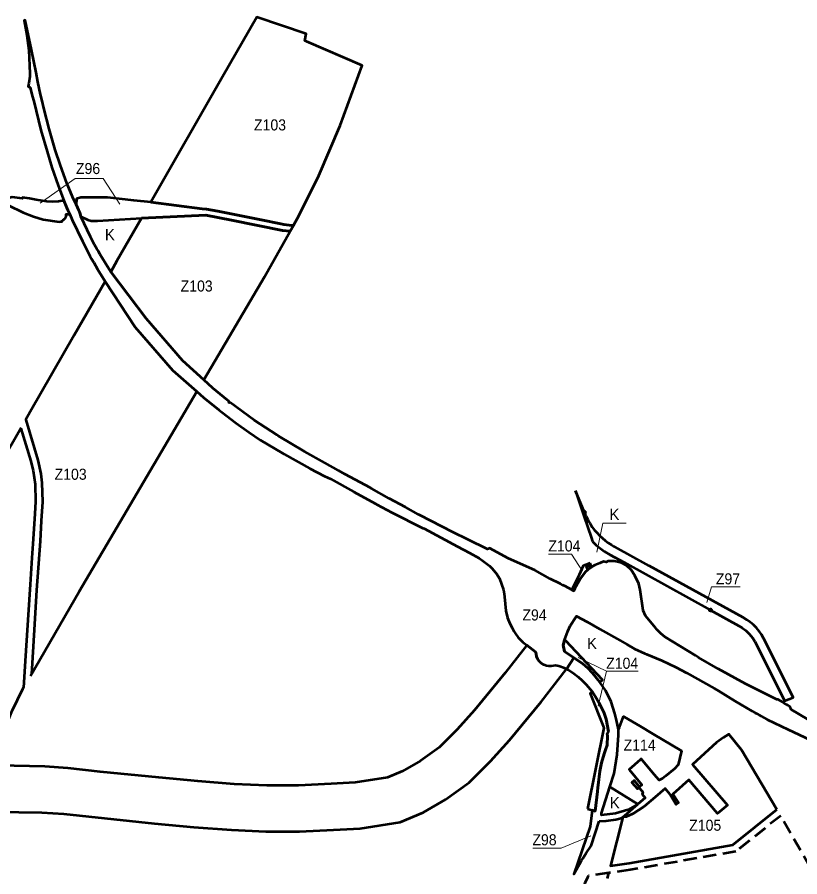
# Model space of a CAD drawing. Extents: x -650246 to -642674, y -1074280 to -1066767.
# Drawn here: x -647810 to -646112, y -1069193 to -1067326 of the extents above; entities that cross this region are included whole.
import ezdxf

# ---------------------------------------------------------------- set-up
doc = ezdxf.new("R2010")
doc.units = 0
doc.header["$LTSCALE"] = 9.6
doc.header["$PDMODE"] = 32
doc.header["$PDSIZE"] = 4.8
doc.linetypes.add('MEDIUM_DASHED', pattern=[4.5, 3, -1.5])
for name, color, linetype, lineweight in [('44', 7, 'Continuous', 53), ('45', 7, 'Continuous', 53), ('46', 7, 'Continuous', 13), ('48', 7, 'Continuous', 13), ('61', 7, 'MEDIUM_DASHED', 53)]:
    doc.layers.add(name, color=color, linetype=linetype, lineweight=lineweight)

msp = doc.modelspace()

# ---------------------------------------------------------------- linework, layer by layer
at = {"layer": '44'}
for p, q in [((-647540.208, -1067762.876), (-647400.63, -1067756.19)), ((-646578.881, -1068401.54), (-646598.635, -1068354.436))]:
    msp.add_line(p, q, dxfattribs=at)
for points in [[(-647606.818, -1067879.061), (-647617.25, -1067861.95), (-647625.37, -1067848.86), (-647630.3, -1067841.02), (-647633.69, -1067834.31), (-647637.21, -1067829.29), (-647642.29, -1067820.76), (-647650.8, -1067803.28), (-647672.05, -1067758.98), (-647673.47, -1067753.48), (-647673.47, -1067753.48), (-647674.67, -1067748.73), (-647676.47, -1067744.5), (-647678.66, -1067739.38), (-647681.91, -1067732.74), (-647690.09, -1067716.05), (-647702.04, -1067686.86), (-647715.92, -1067648.12), (-647727.37, -1067614.33), (-647740.49, -1067568.67), (-647751.41, -1067526.58), (-647756.55, -1067505.32), (-647759.16, -1067494.01), (-647764.89, -1067466.64), (-647768.5, -1067446.04), (-647778.78, -1067397.1), (-647792.52, -1067332.74), (-647794.54, -1067333.14), (-647788.77, -1067365.03), (-647784.55, -1067398.01), (-647782.39, -1067448.34), (-647782.5, -1067455.11), (-647784.36, -1067469.6), (-647785.64, -1067477.02), (-647781.85, -1067479.19), (-647777.55, -1067496.95), (-647773.96, -1067508.48), (-647768.5, -1067529.75), (-647758.25, -1067571.79), (-647744.61, -1067617.96), (-647734.63, -1067652.57), (-647721.05, -1067691.73), (-647708.71, -1067723.99), (-647702.21, -1067740.43), (-647699.89, -1067745.24), (-647697.85, -1067749.46), (-647695.71, -1067753.9), (-647690.19, -1067766.37), (-647668.13, -1067812.76), (-647651.94, -1067844.36), (-647648.33, -1067851.17), (-647643.83, -1067859.13), (-647635.77, -1067873.43), (-647618.773, -1067899.914)], [(-647695.797, -1067753.719), (-647697.85, -1067749.46), (-647699.89, -1067745.24), (-647702.21, -1067740.43), (-647708.71, -1067723.99), (-647720.45, -1067726.49), (-647732.71, -1067727.02), (-647745.41, -1067726.6), (-647768.53, -1067722.82), (-647783.13, -1067719.68), (-647798.17, -1067717.58), (-647798.5, -1067719.67), (-647821.02, -1067717.33), (-647850.45, -1067724.77)], [(-647850.45, -1067724.77), (-647838.18, -1067731.62), (-647832.56, -1067734.22), (-647829.49, -1067734.58), (-647796.87, -1067750.25), (-647774.54, -1067758.68), (-647753.53, -1067765.58), (-647718.54, -1067770.6), (-647712.01, -1067769.63), (-647712.26, -1067767.28)], [(-647520.145, -1067727.879), (-647557, -1067724), (-647614, -1067718), (-647643, -1067718), (-647672, -1067718), (-647680.804, -1067720.745), (-647681.91, -1067732.74)], [(-647681.91, -1067732.74), (-647678.66, -1067739.38), (-647676.47, -1067744.5), (-647674.67, -1067748.73), (-647673.47, -1067753.48)], [(-647398.74, -1067743.15), (-647408.2, -1067742.37), (-647520.145, -1067727.879)], [(-647210.537, -1067778.594), (-647213.92, -1067778.26), (-647231.17, -1067776.55), (-647237.91, -1067775.18), (-647280.78, -1067766.44), (-647374.55, -1067747.34), (-647398.74, -1067743.15)], [(-647712.26, -1067767.28), (-647711.773, -1067767.135), (-647711.286, -1067766.968), (-647710.799, -1067766.777), (-647710.315, -1067766.562), (-647709.834, -1067766.324), (-647709.359, -1067766.062), (-647708.892, -1067765.776), (-647708.433, -1067765.466), (-647707.985, -1067765.133), (-647707.55, -1067764.777), (-647707.128, -1067764.398), (-647706.723, -1067763.999), (-647706.335, -1067763.579), (-647705.966, -1067763.14), (-647705.617, -1067762.683), (-647705.29, -1067762.21), (-647704.985, -1067761.721), (-647704.704, -1067761.22), (-647704.447, -1067760.707), (-647704.216, -1067760.184), (-647704.01, -1067759.653), (-647703.83, -1067759.117), (-647703.675, -1067758.576), (-647703.547, -1067758.033), (-647703.445, -1067757.489), (-647703.368, -1067756.946), (-647703.315, -1067756.406), (-647703.287, -1067755.87), (-647703.282, -1067755.341), (-647703.3, -1067754.818), (-647703.34, -1067754.304), (-647703.4, -1067753.8), (-647695.797, -1067753.719)], [(-647673.47, -1067753.48), (-647672.05, -1067758.98), (-647672.05, -1067758.98), (-647656.469, -1067766.309), (-647649.22, -1067768.38), (-647635.758, -1067768.38), (-647540.208, -1067762.876)], [(-647540.208, -1067762.876), (-647593.267, -1067855.425), (-647606.818, -1067879.061)], [(-647217.611, -1067791.149), (-647233.83, -1067789.69), (-647345.11, -1067767.28), (-647400.63, -1067756.19), (-647540.208, -1067762.876)], [(-647400.63, -1067756.19), (-647345.11, -1067767.28), (-647233.83, -1067789.69), (-647217.611, -1067791.149), (-647210.537, -1067778.594)], [(-647405.026, -1068113.904), (-647273.297, -1067889.981), (-647217.611, -1067791.149)], [(-647405.026, -1068113.904), (-647451.024, -1068071.886), (-647530.038, -1067980.839), (-647606.818, -1067879.061)], [(-647606.818, -1067879.061), (-647530.038, -1067980.839), (-647451.024, -1068071.886), (-647405.026, -1068113.904)], [(-647618.773, -1067899.914), (-647685.819, -1068016.861), (-647781.346, -1068183.485), (-647791.669, -1068201.583)], [(-647781.204, -1068756.329), (-647675.054, -1068572.919), (-647461.188, -1068209.373), (-647419.713, -1068138.871), (-647472.338, -1068093.096), (-647553.628, -1067999.427), (-647618.773, -1067899.915), (-647618.773, -1067899.914)], [(-647618.773, -1067899.914), (-647553.628, -1067999.427), (-647472.338, -1068093.096), (-647419.713, -1068138.871)], [(-646545.57, -1068511.42), (-646556.22, -1068515.84), (-646559.72, -1068517.29), (-646569.61, -1068524.1), (-646572.02, -1068526.07), (-646577.07, -1068530.2), (-646587.28, -1068545.28), (-646599.75, -1068566.49), (-646602.21, -1068571.5), (-646606.59, -1068569.33), (-646620.94, -1068561.96), (-646625.86, -1068559.47), (-646631.18, -1068556.77), (-646653.21, -1068545.58), (-646686.84, -1068526.89), (-646686.84, -1068526.89), (-646743.69, -1068501.76), (-646785.05, -1068479.12), (-646787.55, -1068480.36), (-646789.49, -1068481.31), (-646832.29, -1068460.04), (-646864.48, -1068444.64), (-646936.47, -1068407.23), (-646938.95, -1068405.8), (-646967.64, -1068390), (-647002.71, -1068371.09), (-647040.77, -1068349.4), (-647044.93, -1068347.08), (-647053.75, -1068342.11), (-647099.2, -1068318.27), (-647112.813, -1068310.564), (-647142.41, -1068293.81), (-647186.26, -1068269.45), (-647243.39, -1068235.26), (-647246.8, -1068233.08), (-647295.47, -1068201.09), (-647347.74, -1068162.54), (-647349.59, -1068163.24), (-647350.6, -1068160.26), (-647353.81, -1068157.67), (-647385.13, -1068131.51), (-647405.026, -1068113.904)], [(-647419.713, -1068138.871), (-647405.71, -1068151.74), (-647372.38, -1068179.01), (-647337.74, -1068205.67), (-647334.62, -1068208.02), (-647307.39, -1068227.44), (-647281.64, -1068244.34), (-647234.11, -1068273.04), (-647230.83, -1068274.93), (-647174.56, -1068306.35), (-647142.788, -1068322.462), (-647130.29, -1068328.8), (-647079.16, -1068357.01), (-647032.91, -1068382.51), (-647029.23, -1068384.46), (-646997.06, -1068401.37), (-646929.56, -1068435.42), (-646927.06, -1068436.66)], [(-647791.055, -1068200.507), (-647765.22, -1068287.94), (-647758.45, -1068317.66), (-647756.09, -1068337.61), (-647754.99, -1068378.21), (-647757.41, -1068419.98), (-647760.22, -1068463.96), (-647768.02, -1068570.36), (-647772.85, -1068656.41), (-647778.967, -1068752.463)], [(-647801.168, -1068218.237), (-647843.6, -1068292.629), (-647868.214, -1068337.803), (-647914.339, -1068432.512), (-647946.187, -1068510.254), (-647971.074, -1068581.98), (-647997.27, -1068674.747), (-648011.775, -1068739.718), (-648023.914, -1068809.332), (-648030.73, -1068861.213), (-648038.596, -1068968.281), (-647958.168, -1068957.73)], [(-647801.797, -1068219.339), (-647780.07, -1068290.53), (-647774.94, -1068311.47), (-647770.81, -1068340.29), (-647770.12, -1068377.5), (-647771.74, -1068404.5), (-647775.82, -1068469.74), (-647778.24, -1068499.95), (-647781.55, -1068558.38), (-647785.79, -1068623.98), (-647791.77, -1068713.23), (-647796.139, -1068781.67)], [(-646598.635, -1068354.436), (-646579.62, -1068411.29), (-646564.78, -1068455.41), (-646561.544, -1068464.842)], [(-646927.06, -1068436.66), (-646854.18, -1068475.8), (-646828.2, -1068489.61), (-646807.82, -1068501.17), (-646799.79, -1068506.39), (-646790.66, -1068513.24), (-646785.34, -1068517.77), (-646779.93, -1068522.9), (-646775.44, -1068527.74), (-646768.95, -1068535.8), (-646763.1, -1068545.18), (-646754.92, -1068569.81), (-646753.35, -1068578.6), (-646752.59, -1068584.55), (-646749.35, -1068615.18), (-646746.32, -1068630.23), (-646740.91, -1068642.34), (-646735.62, -1068652.21), (-646732.25, -1068659.06), (-646729.34, -1068663.94), (-646722.6, -1068673.11), (-646716.39, -1068679.8), (-646716.39, -1068679.8), (-646712.93, -1068683), (-646704.316, -1068689.698), (-646684.7, -1068704.95), (-646682.98, -1068714.07), (-646680.88, -1068719.28), (-646678.08, -1068723.7)], [(-646561.544, -1068464.842), (-646553.677, -1068472.283), (-646544.525, -1068479.79), (-646535.245, -1068486.342), (-646523.105, -1068493.54), (-646493.511, -1068509.855), (-646305.678, -1068613.404)], [(-646234.342, -1068629.893), (-646234.342, -1068629.892), (-646438.626, -1068517.274), (-646513.45, -1068476.025), (-646513.567, -1068475.963)], [(-646337.93, -1068712.4), (-646404.83, -1068671.52), (-646413.45, -1068664.71), (-646422.32, -1068655.58), (-646425.11, -1068652.37), (-646446.54, -1068626.14), (-646451.82, -1068614.31), (-646458.03, -1068569.26), (-646461.14, -1068556.34), (-646469.51, -1068538.15), (-646477.41, -1068526.45), (-646487.92, -1068516.87), (-646498.48, -1068511.26), (-646507.4, -1068508.45), (-646514.39, -1068507.56), (-646528.18, -1068507.58), (-646531.9, -1068509.25), (-646537.71, -1068508.16), (-646545.57, -1068511.42)], [(-646305.678, -1068613.404), (-646243.997, -1068647.407), (-646236.707, -1068651.891), (-646228.691, -1068658.051), (-646221.348, -1068665.144), (-646213.659, -1068674.696), (-646209.179, -1068681.795), (-646204.654, -1068690.937), (-646145.083, -1068810.83), (-646126.317, -1068803.654), (-646186.371, -1068682.825)], [(-646602.095, -1068716.98), (-646622.01, -1068703.3), (-646625.35, -1068689.7), (-646622.68, -1068678.75), (-646615.19, -1068659.11), (-646609.7, -1068647.84), (-646597.4, -1068628.74), (-646596.28, -1068626.52), (-646596.28, -1068626.52), (-646573.14, -1068638.98), (-646545.73, -1068654.81), (-646545.73, -1068654.81), (-646501.64, -1068679.81), (-646486.23, -1068688.54), (-646470.65, -1068697.38), (-646448.02, -1068707.99), (-646444.51, -1068709.64), (-646411.3, -1068723.11), (-646380.94, -1068737.81), (-646357.87, -1068749.64), (-646297.08, -1068783.8), (-646288.37, -1068789.04), (-646251.73, -1068811.04), (-646214.92, -1068832.85), (-646208.7, -1068836.39), (-646205.48, -1068838.23), (-646199.24, -1068841.79), (-646195.52, -1068843.92), (-646182.57, -1068851.3), (-646137.23, -1068872.6), (-646089.63, -1068895.5)], [(-646704.316, -1068689.698), (-646725.374, -1068716.786), (-646751.116, -1068749.975), (-646817.718, -1068830.545), (-646855.506, -1068872.883), (-646894.206, -1068911.595), (-646934.465, -1068940.759)], [(-646617.991, -1068741.504), (-646622.62, -1068739.32), (-646634.37, -1068735.27), (-646642.04, -1068733.74), (-646651.21, -1068734.99), (-646656.47, -1068735.13), (-646661.5, -1068734.35), (-646667.17, -1068732.38), (-646673.16, -1068728.69), (-646678.08, -1068723.7), (-646680.88, -1068719.28), (-646682.98, -1068714.07), (-646684.7, -1068704.95), (-646704.316, -1068689.698)], [(-646075.56, -1068861.95), (-646130.68, -1068829.21), (-646132.62, -1068823.54), (-646136.99, -1068820.88), (-646140.73, -1068818.61), (-646146.85, -1068814.88), (-646150.26, -1068812.81), (-646159.1, -1068807.43), (-646161.45, -1068807.54), (-646229.44, -1068773.53), (-646288.59, -1068740.88), (-646331.26, -1068716.25), (-646337.93, -1068712.4)], [(-646618.655, -1068742.359), (-646617.991, -1068741.504), (-646617.991, -1068741.503), (-646602.095, -1068716.98)], [(-646539.08, -1068779.481), (-646545.32, -1068769.89), (-646561.5, -1068750.22), (-646571.91, -1068739.54), (-646583.49, -1068729.76), (-646602.095, -1068716.98), (-646617.991, -1068741.503)], [(-647065.688, -1069087.73), (-646978.92, -1069073.93), (-646929.186, -1069052.925), (-646880.163, -1069024.903), (-646829.104, -1068987.917), (-646782.784, -1068941.581), (-646741.85, -1068895.719), (-646673.05, -1068812.491), (-646618.655, -1068742.359), (-646617.991, -1068741.504)], [(-646617.991, -1068741.503), (-646613.44, -1068743.65), (-646601.86, -1068751.01), (-646592.53, -1068758.66), (-646583.98, -1068766.42), (-646575.28, -1068775.04), (-646562.49, -1068790.69), (-646554.8, -1068801.98)], [(-647864.531, -1068951.823), (-647846.989, -1068896.545), (-647820.883, -1068832.117), (-647797.632, -1068784.713), (-647795.185, -1068780.485)], [(-646509.323, -1068852.529), (-646513.27, -1068838.37), (-646521.18, -1068812.95), (-646532.92, -1068788.95), (-646539.08, -1068779.481)], [(-646554.8, -1068801.98), (-646547.68, -1068814.22), (-646547.433, -1068814.73)], [(-646547.433, -1068814.73), (-646537.35, -1068835.56), (-646532.16, -1068850.47), (-646526.64, -1068877.47), (-646530.06, -1068882.16)], [(-646524, -1068997), (-646514.91, -1068968.48), (-646514.91, -1068968.48), (-646512.07, -1068954.68), (-646507.91, -1068927.47), (-646505.12, -1068885.31), (-646505.17, -1068872.78), (-646509.323, -1068852.529)], [(-646530.06, -1068882.16), (-646528.92, -1068886.55), (-646529.44, -1068906.81), (-646533.28, -1068917.17)], [(-646533.28, -1068917.17), (-646536.54, -1068925.95), (-646542.16, -1068945.12), (-646545.42, -1068963.3), (-646549.17, -1068993.71), (-646549.81, -1068998.88), (-646550.89, -1069007.7), (-646555.84, -1069050.22), (-646559.8, -1069048.98), (-646562.61, -1069048.08)], [(-647749.978, -1068953.416), (-647850.043, -1068951.099), (-647864.531, -1068951.823), (-647895.901, -1068953.392), (-647958.168, -1068957.73), (-648038.596, -1068968.281), (-648038.596, -1068968.281), (-648038.746, -1068968.301), (-648058.764, -1068970.927)], [(-646934.465, -1068940.759), (-646973.61, -1068963.135), (-647006.63, -1068977.08), (-647076.422, -1068988.18), (-647128.674, -1068991.167), (-647199.672, -1068994.255), (-647268.348, -1068994.255), (-647338.816, -1068991.19), (-647417.895, -1068984.986), (-647502.412, -1068977.157), (-647629.424, -1068964.608), (-647699.561, -1068956.635), (-647749.978, -1068953.416)], [(-646462.98, -1069034.61), (-646485, -1069047), (-646512, -1069055), (-646542, -1069059), (-646541.71, -1069054.76), (-646524, -1068997)], [(-647886.615, -1069053.052), (-647856.541, -1069051.548), (-647756.441, -1069053.207), (-647708.401, -1069056.275), (-647511.94, -1069076.703), (-647426.417, -1069084.624), (-647344.902, -1069091.02), (-647270.522, -1069094.255), (-647197.498, -1069094.255), (-647123.648, -1069091.043), (-647065.688, -1069087.73)], [(-646562.61, -1069048.08), (-646566.82, -1069083.62), (-646601.82, -1069187.25), (-646586.97, -1069160.06), (-646585.42, -1069157.56), (-646583.89, -1069155.1), (-646582.46, -1069152.81), (-646582.46, -1069152.81), (-646575.4, -1069141.46), (-646564.54, -1069125.08), (-646547.412, -1069071.71)], [(-646547.412, -1069071.71), (-646532, -1069071), (-646511, -1069068), (-646502, -1069066), (-646496.317, -1069063.61), (-646462.98, -1069034.61)]]:
    msp.add_lwpolyline(points, dxfattribs=at)
msp.add_lwpolyline([(-647520.145, -1067727.879), (-647408.2, -1067742.37), (-647398.74, -1067743.15), (-647374.55, -1067747.34), (-647280.78, -1067766.44), (-647237.91, -1067775.18), (-647231.17, -1067776.55), (-647213.92, -1067778.26), (-647210.537, -1067778.594), (-647198.088, -1067756.5), (-647155.592, -1067670.17), (-647108.971, -1067561.55), (-647061.252, -1067430.908), (-647181.878, -1067379.12), (-647185.93, -1067377.38), (-647183.09, -1067362.16), (-647289.924, -1067326.309), (-647364.024, -1067455.561)], close=True, dxfattribs=at)
at = {"layer": '44', "lineweight": 13}
for points in [[(-647586.774, -1067732.166), (-647623.463, -1067676.175), (-647684.001, -1067676.175), (-647760.132, -1067730.33)], [(-647586.774, -1067732.166), (-647623.463, -1067676.175), (-647684.001, -1067676.175), (-647760.132, -1067730.33)], [(-646241.379, -1068562.947), (-646303.746, -1068562.947), (-646313.477, -1068597.03)], [(-646241.379, -1068562.947), (-646303.746, -1068562.947), (-646313.477, -1068597.03)], [(-646691.216, -1069130.395), (-646629.734, -1069130.395), (-646565.156, -1069103.837)], [(-646691.216, -1069130.395), (-646629.734, -1069130.395), (-646565.156, -1069103.837)]]:
    msp.add_lwpolyline(points, dxfattribs=at)
at = {"layer": '44'}
for centre, radius, start, end in [((-646447.332, -1068351.964), 140.58, 200.6496, 215.36619), ((-646447.332, -1068351.964), 140.58, 215.36631, 241.891), ((-646287.447, -1068726.224), 110, 23.23727, 61.13296)]:
    msp.add_arc(centre, radius, start, end, dxfattribs=at)
for p in [(-646578.881, -1068401.54), (-646305.678, -1068613.404)]:
    msp.add_point(p, dxfattribs=at)
at = {"layer": '45'}
msp.add_line((-646583.49, -1068729.76), (-646571.91, -1068739.54), dxfattribs=at)
msp.add_line((-646583.49, -1068729.76), (-646571.91, -1068739.54), dxfattribs=at)
for points in [[(-646566.33, -1068512.04), (-646581.64, -1068517.24), (-646590.31, -1068536.69), (-646602.01, -1068560.15), (-646606.59, -1068569.33)], [(-646566.33, -1068512.04), (-646581.64, -1068517.24), (-646590.31, -1068536.69), (-646602.01, -1068560.15), (-646606.59, -1068569.33)], [(-646587.28, -1068545.28), (-646577.07, -1068530.2), (-646572.02, -1068526.07), (-646574.48, -1068518.75), (-646565.04, -1068515.86), (-646566.33, -1068512.04)], [(-646587.28, -1068545.28), (-646577.07, -1068530.2), (-646572.02, -1068526.07), (-646574.48, -1068518.75), (-646565.04, -1068515.86), (-646566.33, -1068512.04)], [(-646599.75, -1068566.49), (-646587.28, -1068545.28), (-646587.28, -1068545.28)], [(-646599.75, -1068566.49), (-646587.28, -1068545.28), (-646587.28, -1068545.28)], [(-646606.59, -1068569.33), (-646602.21, -1068571.5), (-646599.75, -1068566.49)], [(-646606.59, -1068569.33), (-646602.21, -1068571.5), (-646599.75, -1068566.49)], [(-646571.91, -1068739.54), (-646561.5, -1068750.22), (-646545.32, -1068769.89), (-646539.78, -1068764.65), (-646596.93, -1068704.15), (-646619.74, -1068680.15), (-646622.68, -1068678.75), (-646625.35, -1068689.7)], [(-646571.91, -1068739.54), (-646561.5, -1068750.22), (-646545.32, -1068769.89), (-646539.78, -1068764.65), (-646596.93, -1068704.15), (-646619.74, -1068680.15), (-646622.68, -1068678.75), (-646625.35, -1068689.7)], [(-646625.35, -1068689.7), (-646622.01, -1068703.3), (-646583.49, -1068729.76)], [(-646625.35, -1068689.7), (-646622.01, -1068703.3), (-646583.49, -1068729.76)], [(-646562.49, -1068790.69), (-646566.34, -1068794.32), (-646537.3, -1068868.95), (-646572.42, -1069044.94)], [(-646562.49, -1068790.69), (-646566.34, -1068794.32), (-646537.3, -1068868.95), (-646572.42, -1069044.94)], [(-646526.64, -1068877.47), (-646532.16, -1068850.47), (-646537.35, -1068835.56), (-646547.68, -1068814.22), (-646554.8, -1068801.98), (-646562.49, -1068790.69)], [(-646526.64, -1068877.47), (-646532.16, -1068850.47), (-646537.35, -1068835.56), (-646547.68, -1068814.22), (-646554.8, -1068801.98), (-646562.49, -1068790.69)], [(-646529.44, -1068906.81), (-646528.92, -1068886.55), (-646530.06, -1068882.16), (-646526.64, -1068877.47)], [(-646529.44, -1068906.81), (-646528.92, -1068886.55), (-646530.06, -1068882.16), (-646526.64, -1068877.47)], [(-646555.84, -1069050.22), (-646550.89, -1069007.7), (-646549.81, -1068998.88), (-646549.17, -1068993.71), (-646545.42, -1068963.3), (-646542.16, -1068945.12), (-646536.54, -1068925.95), (-646533.28, -1068917.17), (-646529.44, -1068906.81)], [(-646555.84, -1069050.22), (-646550.89, -1069007.7), (-646549.81, -1068998.88), (-646549.17, -1068993.71), (-646545.42, -1068963.3), (-646542.16, -1068945.12), (-646536.54, -1068925.95), (-646533.28, -1068917.17), (-646529.44, -1068906.81)], [(-646572.42, -1069044.94), (-646562.61, -1069048.08), (-646559.8, -1069048.98), (-646555.84, -1069050.22)], [(-646572.42, -1069044.94), (-646562.61, -1069048.08), (-646559.8, -1069048.98), (-646555.84, -1069050.22)]]:
    msp.add_lwpolyline(points, dxfattribs=at)
for points in [[(-646512.07, -1068954.68), (-646507.91, -1068927.47), (-646505.12, -1068885.31), (-646505.17, -1068872.78), (-646503.24, -1068867.61), (-646494.52, -1068844.29), (-646492.73, -1068845.01), (-646457.86, -1068865.8), (-646430.86, -1068881.89), (-646368.3, -1068919.19), (-646376.02, -1068949.34), (-646383.86, -1068958.24), (-646403.13, -1068974.41), (-646409.67, -1068979.3), (-646416.71, -1068983.21), (-646427.77, -1068970.39), (-646455.78, -1068936.87), (-646458.21, -1068938.99), (-646482.2, -1068959.52), (-646454.21, -1068992.73), (-646459.25, -1068996.98), (-646471.24, -1068983.41), (-646476.35, -1068987.98), (-646464.24, -1069001.49), (-646461.29, -1068998.81), (-646453.48, -1069006.75), (-646452.37, -1069010.01), (-646453.88, -1069013.1), (-646447.2, -1069020.9), (-646462.98, -1069034.61), (-646524, -1068997), (-646514.91, -1068968.48), (-646514.91, -1068968.48)], [(-646512.07, -1068954.68), (-646507.91, -1068927.47), (-646505.12, -1068885.31), (-646505.17, -1068872.78), (-646503.24, -1068867.61), (-646494.52, -1068844.29), (-646492.73, -1068845.01), (-646457.86, -1068865.8), (-646430.86, -1068881.89), (-646368.3, -1068919.19), (-646376.02, -1068949.34), (-646383.86, -1068958.24), (-646403.13, -1068974.41), (-646409.67, -1068979.3), (-646416.71, -1068983.21), (-646427.77, -1068970.39), (-646455.78, -1068936.87), (-646458.21, -1068938.99), (-646482.2, -1068959.52), (-646454.21, -1068992.73), (-646459.25, -1068996.98), (-646471.24, -1068983.41), (-646476.35, -1068987.98), (-646464.24, -1069001.49), (-646461.29, -1068998.81), (-646453.48, -1069006.75), (-646452.37, -1069010.01), (-646453.88, -1069013.1), (-646447.2, -1069020.9), (-646462.98, -1069034.61), (-646524, -1068997), (-646514.91, -1068968.48), (-646514.91, -1068968.48)], [(-646161.484, -1069046.228), (-646238.632, -1068916.799), (-646266.118, -1068883.048), (-646277.268, -1068890.446), (-646292.75, -1068900.72), (-646344.49, -1068948.736), (-646268.528, -1069036.82), (-646290.099, -1069055.423), (-646352.71, -1068981.82), (-646386.936, -1069012.936), (-646375.346, -1069032.07), (-646379.973, -1069035.889), (-646393.09, -1069014.234), (-646404.269, -1069001.033), (-646425.52, -1069019.41), (-646449.418, -1069039.804), (-646474.13, -1069055.83), (-646488.537, -1069062.169), (-646495.89, -1069063.531), (-646522.35, -1069168.648), (-646482.211, -1069162.813), (-646256.824, -1069123.414)], [(-646161.484, -1069046.228), (-646238.632, -1068916.799), (-646266.118, -1068883.048), (-646277.268, -1068890.446), (-646292.75, -1068900.72), (-646344.49, -1068948.736), (-646268.528, -1069036.82), (-646290.099, -1069055.423), (-646352.71, -1068981.82), (-646386.936, -1069012.936), (-646375.346, -1069032.07), (-646379.973, -1069035.889), (-646393.09, -1069014.234), (-646404.269, -1069001.033), (-646425.52, -1069019.41), (-646449.418, -1069039.804), (-646474.13, -1069055.83), (-646488.537, -1069062.169), (-646495.89, -1069063.531), (-646522.35, -1069168.648), (-646482.211, -1069162.813), (-646256.824, -1069123.414)]]:
    msp.add_lwpolyline(points, close=True, dxfattribs=at)
at = {"layer": '46'}
for points in [[(-646656.853, -1068492.089), (-646606.877, -1068492.089), (-646583.419, -1068529.344)], [(-646656.853, -1068492.089), (-646606.877, -1068492.089), (-646583.419, -1068529.344)], [(-646462.83, -1068746.366), (-646531.233, -1068746.366), (-646549.233, -1068822.328), (-646531.233, -1068746.366), (-646592.58, -1068716.54)], [(-646462.83, -1068746.366), (-646531.233, -1068746.366), (-646549.233, -1068822.328), (-646531.233, -1068746.366), (-646592.58, -1068716.54)]]:
    msp.add_lwpolyline(points, dxfattribs=at)
at = {"layer": '48'}
msp.add_lwpolyline([(-646488.64, -1068425), (-646538.869, -1068425), (-646552.014, -1068487.951)], dxfattribs=at)
msp.add_lwpolyline([(-646488.64, -1068425), (-646538.869, -1068425), (-646552.014, -1068487.951)], dxfattribs=at)
at = {"layer": '61'}
for points in [[(-646583.457, -1069759.191), (-646554.262, -1069762.602), (-646321.973, -1069686.855), (-646209.9, -1069538.5), (-646146.8, -1069506.6), (-646148.5, -1069503), (-646028.16, -1069441.58), (-646023.96, -1069440.34), (-646075.49, -1069318.19), (-646025.14, -1069285.394), (-646153.307, -1069059.947)], [(-646153.307, -1069059.947), (-646250.409, -1069137.52), (-646479.84, -1069177.626), (-646526.31, -1069184.381)]]:
    msp.add_lwpolyline(points, dxfattribs=at)
msp.add_lwpolyline([(-646572.586, -1069194.485), (-646577.878, -1069206.485), (-646611.107, -1069309.68), (-646626.774, -1069359.349), (-646580.797, -1069364.111), (-646571.479, -1069363.822), (-646526.31, -1069184.381), (-646570.296, -1069190.776)], close=True, dxfattribs=at)

# ---------------------------------------------------------------- texts
at = {"layer": '44', "width": 0.95}
for s, p in [('Z103', (-647295.975, -1067572.121)), ('Z103', (-647295.975, -1067572.121)), ('Z96', (-647682.294, -1067666.856)), ('Z96', (-647682.294, -1067666.856)), ('Z103', (-647455.179, -1067921.933)), ('Z103', (-647455.179, -1067921.933)), ('Z103', (-647728.595, -1068330.624)), ('Z103', (-647728.595, -1068330.624)), ('Z97', (-646293.907, -1068557.715)), ('Z97', (-646293.907, -1068557.715)), ('Z94', (-646713.687, -1068636.144)), ('Z94', (-646713.687, -1068636.144)), ('Z98', (-646691.993, -1069124.279)), ('Z98', (-646691.993, -1069124.279))]:
    msp.add_text(s, height=24, dxfattribs=at).set_placement(p)
at = {"layer": '46', "width": 0.95}
for s, p in [('Z104', (-646657.338, -1068486.184)), ('Z104', (-646657.338, -1068486.184)), ('Z104', (-646531.893, -1068740.983)), ('Z104', (-646531.893, -1068740.983)), ('Z114', (-646493.997, -1068918.587)), ('Z114', (-646493.997, -1068918.587)), ('Z105', (-646351.762, -1069092.692)), ('Z105', (-646351.762, -1069092.692))]:
    msp.add_text(s, height=24, dxfattribs=at).set_placement(p)
at = {"layer": '48'}
for p in [(-647619.44, -1067810.434), (-646524.8, -1068417.662), (-646524.8, -1068417.662), (-646573.463, -1068697.908), (-646573.463, -1068697.908), (-646524.065, -1069043.743), (-646524.065, -1069043.743)]:
    msp.add_text('K', height=24, dxfattribs=at).set_placement(p)

doc.saveas('drawing.dxf')
